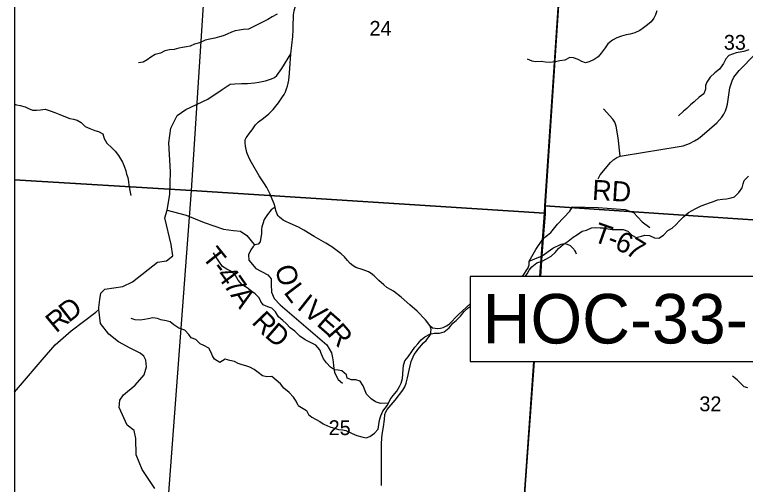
# Model space of a CAD drawing. Extents: x 39.8 to 73.8, y 13 to 35.
# Drawn here: x 41.863 to 43.927, y 29.389 to 30.717 of the extents above; entities that cross this region are included whole.
import ezdxf

# ---------------------------------------------------------------- set-up
doc = ezdxf.new("R2010")
doc.units = 0
for name, color, linetype in [('GM_X_Corporation', 7, 'Continuous'), ('GM_X_County_Road', 7, 'Continuous'), ('GM_X_Minor_River', 7, 'Continuous'), ('GM_X_Section_Text', 7, 'Continuous'), ('GM_X_Township_Road', 7, 'Continuous'), ('GM_X_Township_Road_Text', 7, 'Continuous'), ('TX_P_1', 7, 'Continuous')]:
    doc.layers.add(name, color=color, linetype=linetype)

msp = doc.modelspace()

# ---------------------------------------------------------------- linework, layer by layer
at = {"layer": 'GM_X_Corporation'}
for points in [[(43.3481, 29.9766), (43.3525, 30.036), (43.3561, 30.0855), (43.3611, 30.1536), (43.3611, 30.1764), (43.4119, 30.9413), (43.4278, 31.1804), (43.4594, 31.6102), (43.4604, 31.6234), (43.4879, 31.9992), (43.5004, 32.1696), (43.5417, 32.788), (43.542, 32.7932), (43.5449, 32.8368), (43.546, 32.8532), (43.5465, 32.861), (43.5681, 33.1854), (43.5817, 33.4098), (43.6158, 33.865), (41.863, 33.865), (41.863, 28.2309)], [(48.663, 33.865), (43.6158, 33.865), (43.5817, 33.4098), (43.5681, 33.1854), (43.5465, 32.861), (43.546, 32.8532), (43.5449, 32.8368), (43.542, 32.7932), (43.5417, 32.788), (43.5004, 32.1696), (43.4879, 31.9992), (43.4604, 31.6234), (43.4594, 31.6102), (43.4278, 31.1804), (43.4119, 30.9413), (43.3611, 30.1764), (43.3611, 30.1536), (43.3561, 30.0855), (43.3525, 30.036), (43.3481, 29.9766)], [(43.3298, 29.7365), (43.2893, 29.1598), (42.2872, 29.2147), (42.3628, 30.2201), (43.3592, 30.1556), (43.3467, 29.9766)], [(43.3467, 29.9766), (43.3592, 30.1556), (43.3604, 30.1765), (44.3673, 30.1087), (44.3588, 29.9766)], [(43.3304, 29.7365), (43.2726, 28.9503), (43.2721, 28.9438), (43.2131, 28.1416), (43.9992, 28.0883), (44.127, 28.0796), (44.1422, 28.0786), (45.3064, 27.9996), (46.1767, 27.9406), (46.6011, 27.9118), (46.7316, 27.9029), (46.7775, 27.8998), (46.7905, 27.899), (47.095, 27.8783), (47.5149, 27.8498)], [(43.2726, 28.9503), (43.3304, 29.7365)], [(44.3051, 29.1497), (44.3, 29.0715), (43.2893, 29.1598), (43.3298, 29.7365)]]:
    msp.add_lwpolyline(points, dxfattribs=at)
for points in [[(41.863, 31.2545), (41.863, 30.2506), (42.3628, 30.2201), (42.4262, 31.2112)], [(43.4282, 31.1846), (43.3604, 30.1765), (43.3592, 30.1556), (42.3628, 30.2201), (42.4262, 31.2112)], [(44.4392, 31.1377), (44.3673, 30.1087), (43.3604, 30.1765), (43.4282, 31.1846)], [(41.863, 30.2506), (41.863, 29.2403), (42.2872, 29.2147), (42.3628, 30.2201)]]:
    msp.add_lwpolyline(points, close=True, dxfattribs=at)
at = {"layer": 'GM_X_County_Road'}
for points in [[(42.6428, 30.6063), (42.6486, 30.6553), (42.6496, 30.6738), (42.6498, 30.6916), (42.6505, 30.7069), (42.6508, 30.7167), (42.6529, 30.728), (42.6562, 30.7422), (42.6585, 30.7521), (42.6592, 30.765), (42.6602, 30.7952), (42.6602, 30.807), (42.6612, 30.8196), (42.6613, 30.8205), (42.6602, 30.8402), (42.6588, 30.8469), (42.6571, 30.8534), (42.6538, 30.8613), (42.6499, 30.8697), (42.6431, 30.8805)], [(43.036, 29.8385), (43.0233, 29.8544), (43.0003, 29.879), (42.9797, 29.8971), (42.9551, 29.9184), (42.9328, 29.9358), (42.9243, 29.9405), (42.9147, 29.9463), (42.9058, 29.9531), (42.8916, 29.966), (42.8786, 29.9785), (42.87, 29.9859), (42.8628, 29.9902), (42.8554, 29.9933), (42.847, 29.9963), (42.8271, 30.0029), (42.8194, 30.0068), (42.8106, 30.0139), (42.8031, 30.0218), (42.7943, 30.0326), (42.7849, 30.0415), (42.7591, 30.0608), (42.742, 30.071), (42.7094, 30.0896), (42.6801, 30.1076), (42.6646, 30.1161), (42.6493, 30.1233), (42.639, 30.1275), (42.6309, 30.1313), (42.6215, 30.1367), (42.6166, 30.1404), (42.6114, 30.1449), (42.6078, 30.1482), (42.6048, 30.1533), (42.6011, 30.1639), (42.599, 30.1726), (42.5961, 30.1826), (42.5905, 30.196), (42.5844, 30.2094), (42.5753, 30.2286), (42.5692, 30.2387), (42.554, 30.2614), (42.5322, 30.299), (42.5254, 30.3116), (42.519, 30.3276), (42.5155, 30.3454), (42.5146, 30.3545), (42.5137, 30.3585), (42.5142, 30.3633), (42.5166, 30.3686), (42.5199, 30.3726), (42.5263, 30.3817), (42.5335, 30.3915), (42.5438, 30.4059), (42.5519, 30.414), (42.5661, 30.4246), (42.5814, 30.4363), (42.5929, 30.4487), (42.6081, 30.468), (42.62, 30.4851), (42.6239, 30.4915), (42.628, 30.4992), (42.6313, 30.5074), (42.6341, 30.5151), (42.636, 30.5238), (42.6372, 30.5315), (42.6393, 30.5514), (42.6428, 30.6063)], [(43.5114, 30.2534), (43.517, 30.2642), (43.5464, 30.299), (43.5551, 30.3075), (43.5636, 30.3134), (43.5732, 30.317), (43.6419, 30.3285), (43.7344, 30.3437), (43.7509, 30.3467), (43.7687, 30.3531), (43.7836, 30.3603), (43.7942, 30.3673), (43.8052, 30.3751), (43.8464, 30.4118), (43.86, 30.4269), (43.8659, 30.4356), (43.8704, 30.4451), (43.874, 30.4538), (43.8767, 30.4642), (43.8814, 30.4973), (43.8835, 30.5098), (43.8865, 30.5213), (43.8897, 30.5304), (43.8947, 30.5404), (43.9017, 30.5501), (43.9092, 30.5597), (43.955, 30.6057)], [(43.5732, 30.317), (43.5677, 30.3692), (43.5617, 30.4023), (43.5581, 30.4129), (43.5524, 30.4218), (43.5261, 30.4511)], [(42.8993, 29.3863), (42.8995, 29.4165), (42.899, 29.4624), (42.8995, 29.5018), (42.9005, 29.5217), (42.9025, 29.5363), (42.9051, 29.5523), (42.9073, 29.5731), (42.9087, 29.5867), (42.9113, 29.5944), (42.915, 29.6013), (42.9204, 29.608), (42.9377, 29.6279), (42.9591, 29.6558), (42.9652, 29.6653), (42.9687, 29.6758), (42.9726, 29.6908), (42.9771, 29.7121), (42.9834, 29.7368), (42.9884, 29.7499), (42.9918, 29.7565), (42.9978, 29.765), (43.0019, 29.771), (43.0182, 29.79), (43.025, 29.7958), (43.0305, 29.8023), (43.0339, 29.8071), (43.0373, 29.8127), (43.0386, 29.8197), (43.0392, 29.8268), (43.0386, 29.831), (43.036, 29.8385)]]:
    msp.add_lwpolyline(points, dxfattribs=at)
at = {"layer": 'GM_X_Minor_River'}
for p, q in [((43.6728, 30.7169), (43.6686, 30.7074)), ((43.6769, 30.7278), (43.6728, 30.7169)), ((43.661, 30.6968), (43.6504, 30.6884)), ((43.6686, 30.7074), (43.661, 30.6968)), ((43.6285, 30.6725), (43.6144, 30.6661)), ((43.6391, 30.6801), (43.6285, 30.6725)), ((43.6504, 30.6884), (43.6391, 30.6801)), ((43.5637, 30.652), (43.552, 30.6452)), ((43.5773, 30.6562), (43.5637, 30.652)), ((43.5902, 30.66), (43.5773, 30.6562)), ((43.6016, 30.6623), (43.5902, 30.66)), ((43.6144, 30.6661), (43.6016, 30.6623)), ((43.5387, 30.6342), (43.5311, 30.6236)), ((43.552, 30.6452), (43.5387, 30.6342)), ((43.5311, 30.6236), (43.5194, 30.6084)), ((43.912, 30.6108), (43.9014, 30.6089)), ((43.9222, 30.6134), (43.912, 30.6108)), ((43.937, 30.6176), (43.9222, 30.6134)), ((43.3244, 30.5853), (43.3119, 30.5917)), ((43.4168, 30.5887), (43.4028, 30.5861)), ((43.4316, 30.5963), (43.4168, 30.5887)), ((43.4418, 30.5955), (43.4316, 30.5963)), ((43.4543, 30.5899), (43.4418, 30.5955)), ((43.4649, 30.5846), (43.4543, 30.5899)), ((43.4997, 30.5902), (43.4853, 30.5838)), ((43.5111, 30.5978), (43.4997, 30.5902)), ((43.5194, 30.6084), (43.5111, 30.5978)), ((43.8719, 30.5918), (43.8647, 30.5786)), ((43.8806, 30.6017), (43.8719, 30.5918)), ((43.8908, 30.6058), (43.8806, 30.6017)), ((43.9014, 30.6089), (43.8908, 30.6058)), ((43.3343, 30.5834), (43.3244, 30.5853)), ((43.3498, 30.5845), (43.3343, 30.5834)), ((43.3623, 30.5826), (43.3498, 30.5845)), ((43.3748, 30.5815), (43.3623, 30.5826)), ((43.3895, 30.5838), (43.3748, 30.5815)), ((43.4028, 30.5861), (43.3895, 30.5838)), ((43.4755, 30.5811), (43.4649, 30.5846)), ((43.4853, 30.5838), (43.4755, 30.5811)), ((43.8647, 30.5786), (43.8541, 30.5634)), ((43.8404, 30.5524), (43.8276, 30.5403)), ((43.8541, 30.5634), (43.8404, 30.5524)), ((43.8177, 30.5266), (43.8147, 30.5171)), ((43.8276, 30.5403), (43.8177, 30.5266)), ((43.8139, 30.5069), (43.8094, 30.4929)), ((43.8147, 30.5171), (43.8139, 30.5069)), ((43.8094, 30.4929), (43.7961, 30.4838)), ((43.7821, 30.4705), (43.7723, 30.4618)), ((43.7961, 30.4838), (43.7821, 30.4705)), ((41.863, 30.464), (41.8684, 30.4623)), ((41.8684, 30.4623), (41.8786, 30.4604)), ((41.8786, 30.4604), (41.8926, 30.4562)), ((41.8926, 30.4562), (41.9024, 30.4521)), ((41.9024, 30.4521), (41.9134, 30.4475)), ((41.9134, 30.4475), (41.9251, 30.4471)), ((41.9251, 30.4471), (41.9357, 30.4483)), ((41.9357, 30.4483), (41.9494, 30.4502)), ((41.9494, 30.4502), (41.963, 30.4449)), ((41.963, 30.4449), (41.9762, 30.4403)), ((43.7522, 30.444), (43.7378, 30.4307)), ((43.762, 30.4523), (43.7522, 30.444)), ((43.7723, 30.4618), (43.762, 30.4523)), ((41.9762, 30.4403), (41.991, 30.435)), ((41.991, 30.435), (42.0065, 30.4282)), ((42.0065, 30.4282), (42.019, 30.4237)), ((42.019, 30.4237), (42.0296, 30.4218)), ((42.0296, 30.4218), (42.0395, 30.4187)), ((42.0395, 30.4187), (42.0512, 30.4127)), ((42.0512, 30.4127), (42.0622, 30.4013)), ((42.0622, 30.4013), (42.0754, 30.3952)), ((42.0754, 30.3952), (42.0898, 30.3899)), ((42.0898, 30.3899), (42.0997, 30.3869)), ((42.0997, 30.3869), (42.1121, 30.3805)), ((42.1121, 30.3805), (42.1163, 30.3672)), ((42.1163, 30.3672), (42.1239, 30.3539)), ((42.1239, 30.3539), (42.1375, 30.341)), ((42.1375, 30.341), (42.147, 30.3308)), ((42.147, 30.3308), (42.1564, 30.3191)), ((42.1564, 30.3191), (42.1625, 30.3096)), ((42.1625, 30.3096), (42.1678, 30.2997)), ((42.1678, 30.2997), (42.1727, 30.2891)), ((42.1727, 30.2891), (42.1772, 30.2759)), ((42.1772, 30.2759), (42.1791, 30.2664)), ((42.1791, 30.2664), (42.1825, 30.2569)), ((42.1825, 30.2569), (42.1848, 30.2444)), ((42.1848, 30.2444), (42.1859, 30.2349)), ((42.1859, 30.2349), (42.1897, 30.2152)), ((42.1897, 30.2152), (42.1908, 30.2058)), ((42.4327, 30.0315), (42.4244, 30.0436)), ((42.4414, 30.0178), (42.4327, 30.0315)), ((42.4501, 30.0053), (42.4414, 30.0178)), ((42.4619, 29.9974), (42.4501, 30.0053)), ((42.4755, 29.9909), (42.4619, 29.9974)), ((42.4872, 29.9799), (42.4755, 29.9909)), ((42.4944, 29.9663), (42.4872, 29.9799)), ((42.5054, 29.953), (42.4944, 29.9663)), ((42.5194, 29.9447), (42.5054, 29.953)), ((42.5326, 29.9348), (42.5194, 29.9447)), ((42.5425, 29.9284), (42.5326, 29.9348)), ((42.5538, 29.9163), (42.5425, 29.9284)), ((42.558, 29.9068), (42.5538, 29.9163)), ((42.5652, 29.8973), (42.558, 29.9068)), ((42.5784, 29.8912), (42.5652, 29.8973)), ((42.589, 29.8875), (42.5784, 29.8912)), ((42.6, 29.8772), (42.589, 29.8875)), ((42.608, 29.8632), (42.6, 29.8772)), ((42.2036, 29.8544), (42.1919, 29.8582)), ((42.2173, 29.8533), (42.2036, 29.8544)), ((42.2301, 29.8552), (42.2173, 29.8533)), ((42.24, 29.8575), (42.2301, 29.8552)), ((42.2532, 29.8605), (42.24, 29.8575)), ((42.2661, 29.8579), (42.2532, 29.8605)), ((42.2763, 29.8548), (42.2661, 29.8579)), ((42.2911, 29.8518), (42.2763, 29.8548)), ((42.3024, 29.8488), (42.2911, 29.8518)), ((42.313, 29.84), (42.3024, 29.8488)), ((42.6201, 29.853), (42.608, 29.8632)), ((42.6303, 29.8446), (42.6201, 29.853)), ((42.327, 29.831), (42.313, 29.84)), ((42.3441, 29.8253), (42.327, 29.831)), ((42.3551, 29.8131), (42.3441, 29.8253)), ((42.6417, 29.8318), (42.6303, 29.8446)), ((42.6541, 29.8227), (42.6417, 29.8318)), ((42.3615, 29.8037), (42.3551, 29.8131)), ((42.6685, 29.8083), (42.6541, 29.8227)), ((42.6837, 29.7977), (42.6685, 29.8083)), ((42.3744, 29.7987), (42.3615, 29.8037)), ((42.3872, 29.787), (42.3744, 29.7987)), ((42.3978, 29.7817), (42.3872, 29.787)), ((42.6984, 29.7901), (42.6837, 29.7977)), ((42.7136, 29.7825), (42.6984, 29.7901)), ((42.4118, 29.7749), (42.3978, 29.7817)), ((42.4183, 29.762), (42.4118, 29.7749)), ((42.7249, 29.77), (42.7136, 29.7825)), ((42.7302, 29.7575), (42.7249, 29.77)), ((42.4217, 29.7525), (42.4183, 29.762)), ((42.4277, 29.743), (42.4217, 29.7525)), ((42.4425, 29.7343), (42.4277, 29.743)), ((42.458, 29.7438), (42.4425, 29.7343)), ((42.4713, 29.7396), (42.458, 29.7438)), ((42.7351, 29.7442), (42.7302, 29.7575)), ((42.7438, 29.7332), (42.7351, 29.7442)), ((42.4838, 29.7366), (42.4713, 29.7396)), ((42.4947, 29.7313), (42.4838, 29.7366)), ((42.5053, 29.7271), (42.4947, 29.7313)), ((42.5156, 29.7245), (42.5053, 29.7271)), ((42.5269, 29.7211), (42.5156, 29.7245)), ((42.7556, 29.7211), (42.7438, 29.7332)), ((42.5394, 29.7143), (42.5269, 29.7211)), ((42.5508, 29.7059), (42.5394, 29.7143)), ((42.5629, 29.6961), (42.5508, 29.7059)), ((42.7666, 29.7135), (42.7556, 29.7211)), ((42.7764, 29.712), (42.7666, 29.7135)), ((42.787, 29.7105), (42.7764, 29.712)), ((42.7999, 29.6995), (42.787, 29.7105)), ((42.5757, 29.6938), (42.5629, 29.6961)), ((42.5894, 29.6946), (42.5757, 29.6938)), ((42.6015, 29.6839), (42.5894, 29.6946)), ((42.614, 29.6737), (42.6015, 29.6839)), ((42.8018, 29.69), (42.7999, 29.6995)), ((42.8142, 29.6847), (42.8018, 29.69)), ((42.8264, 29.6851), (42.8142, 29.6847)), ((42.8392, 29.6809), (42.8264, 29.6851)), ((42.8479, 29.6684), (42.8392, 29.6809)), ((43.9042, 29.6853), (43.8906, 29.6951)), ((43.9137, 29.675), (43.9042, 29.6853)), ((42.6234, 29.6612), (42.614, 29.6737)), ((42.6382, 29.6487), (42.6234, 29.6612)), ((42.8513, 29.659), (42.8479, 29.6684)), ((43.9239, 29.6656), (43.9137, 29.675)), ((43.9341, 29.6622), (43.9239, 29.6656)), ((42.6503, 29.6362), (42.6382, 29.6487)), ((42.857, 29.6446), (42.8513, 29.659)), ((42.8703, 29.6317), (42.857, 29.6446)), ((42.6583, 29.6244), (42.6503, 29.6362)), ((42.6636, 29.6128), (42.6583, 29.6244)), ((42.8824, 29.623), (42.8703, 29.6317)), ((42.896, 29.618), (42.8824, 29.623)), ((42.919, 29.619), (42.896, 29.618)), ((42.6636, 29.6128), (42.6878, 29.5985)), ((42.6878, 29.5985), (42.6928, 29.5867)), ((42.9028, 29.5964), (42.9165, 29.6129)), ((42.6928, 29.5867), (42.7023, 29.5796)), ((42.7023, 29.5796), (42.7125, 29.5735)), ((42.8938, 29.5706), (42.8972, 29.5831)), ((42.8972, 29.5831), (42.9028, 29.5964)), ((42.7125, 29.5735), (42.7247, 29.5675)), ((42.7247, 29.5675), (42.7345, 29.5604)), ((42.7345, 29.5604), (42.747, 29.5548)), ((42.8894, 29.5459), (42.8916, 29.5588)), ((42.8916, 29.5588), (42.8938, 29.5706)), ((42.747, 29.5548), (42.7565, 29.5514)), ((42.7565, 29.5514), (42.7664, 29.548)), ((42.7664, 29.548), (42.7781, 29.545)), ((42.7781, 29.545), (42.7887, 29.5439)), ((42.7887, 29.5439), (42.7986, 29.5417)), ((42.7986, 29.5417), (42.816, 29.5331)), ((42.8796, 29.5341), (42.8894, 29.5459)), ((42.816, 29.5331), (42.8296, 29.5278)), ((42.8296, 29.5278), (42.8433, 29.5241)), ((42.8433, 29.5241), (42.8562, 29.5215)), ((42.8562, 29.5215), (42.8664, 29.525)), ((42.8664, 29.525), (42.8796, 29.5341))]:
    msp.add_line(p, q, dxfattribs=at)
for points in [[(42.6044, 30.7186), (42.5904, 30.7106)], [(42.5904, 30.7106), (42.5779, 30.7034), (42.5646, 30.697), (42.5518, 30.6898), (42.537, 30.683), (42.5234, 30.6765), (42.509, 30.675), (42.4984, 30.6735), (42.4863, 30.6716), (42.4757, 30.6674), (42.4635, 30.6621), (42.4518, 30.6576), (42.442, 30.6545), (42.4287, 30.6507), (42.4147, 30.6477), (42.4015, 30.6447), (42.3855, 30.6378), (42.3712, 30.6333), (42.359, 30.6284), (42.3484, 30.6257), (42.3367, 30.6242), (42.3269, 30.6219), (42.3136, 30.6189), (42.3, 30.6181), (42.2871, 30.6147), (42.275, 30.6079), (42.2602, 30.6045), (42.2477, 30.5965), (42.2375, 30.5893), (42.2262, 30.5825), (42.2133, 30.5806)], [(43.3052, 29.9766), (43.3103, 29.9846), (43.3163, 29.9948), (43.3239, 30.0047), (43.3383, 30.0153), (43.3534, 30.0206), (43.3652, 30.0267), (43.3784, 30.0342), (43.3898, 30.0452), (43.3993, 30.0562), (43.4121, 30.0672), (43.4269, 30.0767), (43.4405, 30.0884), (43.453, 30.096), (43.4659, 30.1048), (43.478, 30.1082), (43.4924, 30.1142), (43.5041, 30.1154), (43.5166, 30.1142), (43.5265, 30.1142), (43.5397, 30.1116), (43.5507, 30.1101), (43.5621, 30.1097), (43.5821, 30.1097), (43.5946, 30.1051), (43.606, 30.0938), (43.6181, 30.0873), (43.6332, 30.0911), (43.6431, 30.0934), (43.6559, 30.093), (43.67, 30.0866), (43.6821, 30.0855), (43.6957, 30.0934), (43.7082, 30.1071), (43.7199, 30.1139), (43.7302, 30.1226), (43.7411, 30.1347), (43.7521, 30.1461), (43.7661, 30.1575), (43.7764, 30.1635), (43.7866, 30.1688), (43.8017, 30.1764), (43.815, 30.1814), (43.826, 30.1855), (43.8369, 30.1893), (43.8483, 30.1935), (43.8627, 30.1958), (43.8737, 30.1965), (43.8865, 30.1992), (43.8964, 30.2022), (43.9081, 30.2143), (43.918, 30.228), (43.9206, 30.2386), (43.9233, 30.2488), (43.9361, 30.2606)], [(42.9165, 29.6129), (42.9233, 29.6294), (42.932, 29.6404), (42.9422, 29.6529), (42.9498, 29.6658), (42.9543, 29.6757), (42.9581, 29.6885), (42.9596, 29.7014), (42.9604, 29.7154), (42.9615, 29.7253), (42.9649, 29.7382), (42.9744, 29.7503), (42.985, 29.7651), (42.9933, 29.7776), (43.0017, 29.7871), (43.0111, 29.7977), (43.0217, 29.8064), (43.0354, 29.8144), (43.0482, 29.8167), (43.063, 29.817), (43.0766, 29.8204), (43.0903, 29.8322), (43.1005, 29.8447), (43.1103, 29.8523), (43.1221, 29.8648), (43.1331, 29.8777), (43.1444, 29.8883), (43.1495, 29.8924)]]:
    msp.add_lwpolyline(points, dxfattribs=at)
at = {"layer": 'GM_X_Township_Road'}
for points in [[(41.863, 29.6502), (41.8795, 29.6695), (41.9411, 29.7415), (41.9776, 29.7836), (42.0229, 29.823), (42.092, 29.8764), (42.1008, 29.884), (42.1011, 29.8893), (42.1035, 29.9124), (42.1069, 29.9302), (42.118, 29.9412), (42.1688, 29.9484), (42.1958, 29.9616), (42.2661, 30.0177), (42.2922, 30.0215), (42.3097, 30.0351), (42.3052, 30.0674), (42.2876, 30.1425), (42.2941, 30.1649), (42.3014, 30.2089), (42.303, 30.2726), (42.299, 30.3546), (42.304, 30.3959), (42.322, 30.4319), (42.3466, 30.4493), (42.4089, 30.4781), (42.4496, 30.5054), (42.4716, 30.5202), (42.4846, 30.5212), (42.5038, 30.5221), (42.5209, 30.5226), (42.5403, 30.524), (42.5526, 30.5259), (42.5713, 30.5303), (42.5884, 30.5355), (42.5971, 30.5397), (42.6034, 30.5451), (42.6175, 30.5653), (42.6428, 30.6063)], [(42.2941, 30.1649), (42.3475, 30.15), (42.3987, 30.1299), (42.4525, 30.1108), (42.4813, 30.107), (42.5014, 30.1047), (42.5189, 30.0929), (42.5399, 30.0679)], [(42.599, 30.1726), (42.5879, 30.1653), (42.5772, 30.1526), (42.568, 30.1383), (42.5636, 30.1262), (42.5614, 30.1173), (42.5605, 30.11), (42.5601, 30.0983), (42.5564, 30.0754), (42.5507, 30.0682), (42.5412, 30.0664)], [(43.3685, 30.0943), (43.3775, 30.1011), (43.3965, 30.1253), (43.4309, 30.1621), (43.439, 30.1737), (43.5111, 30.1716), (43.5878, 30.1665), (43.6108, 30.1576), (43.6354, 30.1317), (43.6573, 30.1156)], [(43.297, 29.9766), (43.313, 30.0018), (43.316, 30.0101), (43.3167, 30.0206), (43.3347, 30.0537), (43.3563, 30.085), (43.3685, 30.0943)], [(42.5399, 30.0679), (42.5412, 30.0664), (42.5366, 30.0614), (42.5298, 30.0527), (42.5237, 30.0387), (42.5244, 30.0231), (42.5445, 30), (42.5786, 29.9817), (42.5873, 29.9703), (42.5876, 29.9643), (42.5876, 29.954), (42.5887, 29.9331), (42.5959, 29.9149), (42.6133, 29.8967), (42.745, 29.7835), (42.7583, 29.7615), (42.7606, 29.7472)], [(43.3167, 30.0206), (43.3527, 30.0355), (43.3833, 30.0575), (43.4065, 30.0688), (43.4159, 30.0701), (43.4235, 30.0684), (43.4324, 30.0642), (43.4423, 30.0546), (43.4446, 30.0503)], [(43.4446, 30.0503), (43.4469, 30.0459), (43.4489, 30.0409)], [(43.036, 29.8385), (43.0436, 29.8324), (43.0509, 29.8307), (43.0577, 29.83), (43.0659, 29.8312), (43.0737, 29.8329), (43.0829, 29.8376), (43.0901, 29.8427), (43.1162, 29.8688), (43.1495, 29.8993)], [(42.2589, 29.3778), (42.2236, 29.432), (42.2065, 29.4733), (42.205, 29.5192), (42.2004, 29.542), (42.1811, 29.5564), (42.1582, 29.607), (42.1601, 29.6274), (42.1704, 29.6422), (42.2031, 29.6703), (42.2286, 29.6995), (42.2358, 29.7216), (42.2332, 29.7408), (42.2281, 29.7523), (42.2173, 29.7606), (42.1893, 29.7746), (42.1567, 29.7921), (42.1294, 29.8137), (42.1052, 29.8441), (42.1008, 29.884)], [(42.7606, 29.7472), (42.7624, 29.7357), (42.7638, 29.7245), (42.7661, 29.7061), (42.7771, 29.6856), (42.7892, 29.6759)]]:
    msp.add_lwpolyline(points, dxfattribs=at)
at = {"layer": 'TX_P_1'}
msp.add_lwpolyline([(43.1495, 29.7365), (44.4854, 29.7365), (44.4854, 29.9766), (43.1495, 29.9766)], close=True, dxfattribs=at)

# ---------------------------------------------------------------- texts
at = {"layer": 'GM_X_Section_Text'}
for s, p in [('24', (42.8653, 30.6574)), ('33', (43.8661, 30.6179)), ('32', (43.797, 29.5962)), ('25', (42.7499, 29.5287))]:
    msp.add_text(s, height=0.04186, rotation=0, dxfattribs=at).set_placement(p)
at = {"layer": 'GM_X_Township_Road_Text'}
for s, height, rotation, p in [('RD', 0.05682, 356.5176, (43.4931, 30.1941)), ('T', 0.0568, 340.5595, (43.4938, 30.0773)), ('6', 0.0568, 336.7556, (43.5549, 30.0554)), ('-', 0.0568, 339.7034, (43.5337, 30.0632)), ('7', 0.0568, 328.565, (43.5851, 30.0426)), ('T', 0.0568, 308.5501, (42.3903, 30.032)), ('-', 0.0568, 307.7114, (42.4166, 29.999)), ('4', 0.0568, 306.3381, (42.4307, 29.9808)), ('O', 0.0568, 284.349, (42.5979, 30.0025)), ('7', 0.0568, 305.044, (42.4512, 29.9529)), ('L', 0.0568, 307.3732, (42.6211, 29.9318)), ('A', 0.0568, 304.0558, (42.4712, 29.9244)), ('D', 0.0568, 37.9191, (42.0158, 29.8451)), ('I', 0.0568, 321.5904, (42.6576, 29.887)), ('V', 0.0568, 319.2774, (42.6754, 29.8729)), ('R', 0.0568, 39.6826, (41.9802, 29.8156)), ('R', 0.0568, 313.9788, (42.5303, 29.8458)), ('E', 0.0568, 318.7907, (42.7132, 29.8404)), ('D', 0.0568, 319.3579, (42.5669, 29.8082)), ('R', 0.0568, 311.1389, (42.7438, 29.8138))]:
    msp.add_text(s, height=height, rotation=rotation, dxfattribs=at).set_placement(p)
at = {"layer": 'TX_P_1'}
msp.add_text('HOC-33-13.13', height=0.14, dxfattribs=at).set_placement((43.185, 29.7877))

doc.saveas('drawing.dxf')
